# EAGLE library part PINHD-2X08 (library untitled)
PIN HEADER
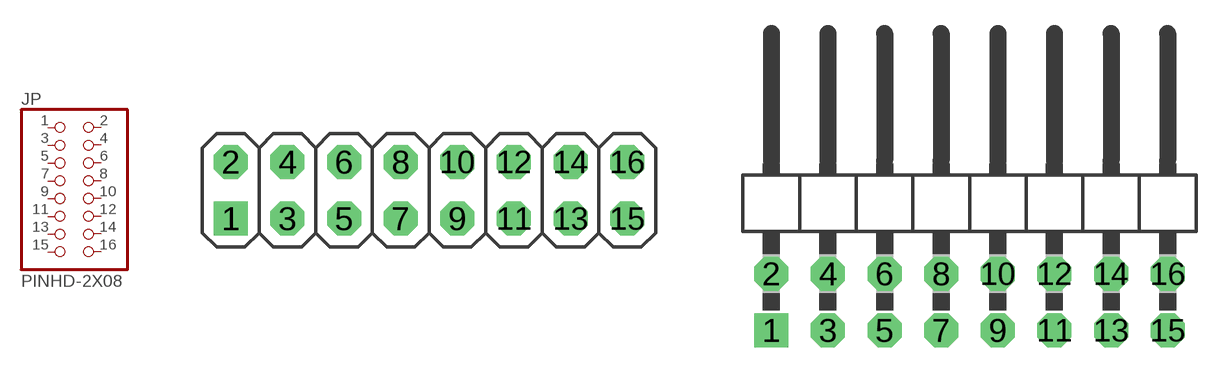
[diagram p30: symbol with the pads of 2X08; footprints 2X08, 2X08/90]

Designator prefix JP

## PINHD-2X08_2.54  [2X08]
1  1  pas
2  2  pas
3  3  pas
4  4  pas
5  5  pas
6  6  pas
7  7  pas
8  8  pas
9  9  pas
10  10  pas
11  11  pas
12  12  pas
13  13  pas
14  14  pas
15  15  pas
16  16  pas

## PINHD-2X08_2.54-90°  [2X08/90]
Pads as for 2X08

## PINHD-2X08_2.00  [2X08M]
Pads as for 2X08

## PINHD-2X08_2.54-SMD  [2X08SMD]
Pads as for 2X08

## PINHD-2X08_MICROMATCH  [MICROMATCH-16]
Pads as for 2X08

## PINHD-2X08_2.54-SMD-90°  [2X08SMD/90]
Pads as for 2X08

## Footprint 2X08 (pad centres in mm)
PIN HEADER - 2.54
drill 1.016 square: 1 -8.89,-1.27
drill 1.016 octagon: 2 -8.89,1.27; 3 -6.35,-1.27; 4 -6.35,1.27; 5 -3.81,-1.27; 6 -3.81,1.27; 7 -1.27,-1.27; 8 -1.27,1.27; 9 1.27,-1.27; 10 1.27,1.27; 11 3.81,-1.27; 12 3.81,1.27; 13 6.35,-1.27; 14 6.35,1.27; 15 8.89,-1.27; 16 8.89,1.27

## Footprint 2X08/90 (pad centres in mm)
PIN HEADER - 2.54 90°
drill 1.016 square: 1 -8.89,-6.35
drill 1.016 octagon: 2 -8.89,-3.81; 3 -6.35,-6.35; 4 -6.35,-3.81; 5 -3.81,-6.35; 6 -3.81,-3.81; 7 -1.27,-6.35; 8 -1.27,-3.81; 9 1.27,-6.35; 10 1.27,-3.81; 11 3.81,-6.35; 12 3.81,-3.81; 13 6.35,-6.35; 14 6.35,-3.81; 15 8.89,-6.35; 16 8.89,-3.81

## Footprint 2X08M (pad centres in mm)
PIN HEADER - 2
drill 0.914 square: 1 -7,-1
drill 0.914 round: 2 -7,1; 3 -5,-1; 4 -5,1; 5 -3,-1; 6 -3,1; 7 -1,-1; 8 -1,1; 9 1,-1; 10 1,1; 11 3,-1; 12 3,1; 13 5,-1; 14 5,1; 15 7,-1; 16 7,1

## Footprint 2X08SMD (pad centres in mm)
PIN HEADER - 2.54 SMD
smd 1.016 x 3.302: 1 -1.27,-3.81; 2 -1.27,1.27; 3 1.27,-3.81; 4 1.27,1.27; 5 3.81,-3.81; 6 3.81,1.27; 7 6.35,-3.81; 8 6.35,1.27; 9 8.89,-3.81; 10 8.89,1.27; 11 11.43,-3.81; 12 11.43,1.27; 13 13.97,-3.81; 14 13.97,1.27; 15 16.51,-3.81; 16 16.51,1.27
